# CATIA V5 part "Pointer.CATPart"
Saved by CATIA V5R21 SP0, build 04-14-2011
Part number: Part2
Bounding box of the stored display mesh (mm): x -12.875 to 12.875, y -12.732 to 12.732, z 0 to 100
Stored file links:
  D:\CATIA V5R21 E-RESOURCES\CATIA-V5R21\catia-v5r21-prt\c16-catia-v5r20-prt\Point Surface Joint-(Fig16-46)\CAT_V5R21_Pointer.CATPart
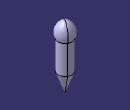
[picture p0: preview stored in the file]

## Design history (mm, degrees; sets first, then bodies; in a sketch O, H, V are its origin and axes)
Body1 (main body)
  Sketch1 on yz-plane, origin (0, 0, 0), H (0, 1, 0), V (0, 0, 1)
    line L1 (0, 0) -> (10.9446, 30.0702)
    point P1 (10.9446, 30.0702)
    line L2 (10.9446, 30.0702) -> (10.9446, 75.0702)
    point P2 (10.9446, 30.0702)
    point P3 (10.9446, 75.0702)
    arc A1 centre (-4.3336, 83.2301) radius 17.3208 from (10.9446, 75.0702) to (0, 100) ccw
    point P5 (0, 100)
    point P6 (10.9446, 91.3901)
    line L3 (0, 0) -> (0, 100)
    reference intersected line E1 through (0, 0) direction (-1, 0) from xy-plane
    reference intersected line E3 through (0, 0) direction (0, 1) from zx-plane
    radius A1 = 17.3208
    angle L1 L3 = 20
    distance O P1 = 32
    distance O P5 = 100
    distance P2 P3 = 45
    coincidence: P2 L1, P5 V, A1 P6, P6 L2, P2 P1, E3 P5, P1 L2
    vertical: L2 V, L3 V, E3 V
    horizontal: E1 H
    perpendicularity: E1 L2
  Shaft1: profile Sketch1, axis Sketch1.L3, angle 360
